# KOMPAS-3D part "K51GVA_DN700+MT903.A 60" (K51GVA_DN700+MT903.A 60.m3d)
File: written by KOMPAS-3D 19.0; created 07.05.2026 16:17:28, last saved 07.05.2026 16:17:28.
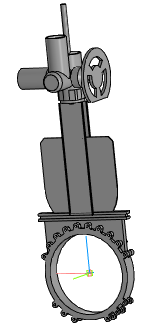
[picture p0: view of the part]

Document properties: Автор: Энергия; Полное имя файла: ..\K51GVA_DN50-DN1000+MT903.A\K51GVA_DN700+MT903.A 60.a3d

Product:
- Part/product: K51GVA_DN700+MT903.A 60
    Масса: 597.27

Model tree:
1. Операция без истории:1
